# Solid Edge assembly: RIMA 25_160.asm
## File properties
Title: Zylinder
Author: ahadarics
Template: iso metric assembly.asm
Last saved by: ahadarics
Revision: 17
Application: Solid Edge
Username: ahadarics
Dokumentum tartalom típus: 1
Document Number: RIMA 25/160
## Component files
Profilrohr.par
Kolbenstange.par
Kit_1.par
Kit_2.par
Mutter_1.par
Mutter_2.par
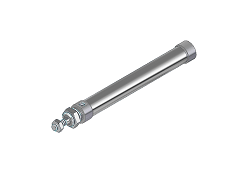
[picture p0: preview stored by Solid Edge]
